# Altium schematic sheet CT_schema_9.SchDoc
size 147 x 119 mm
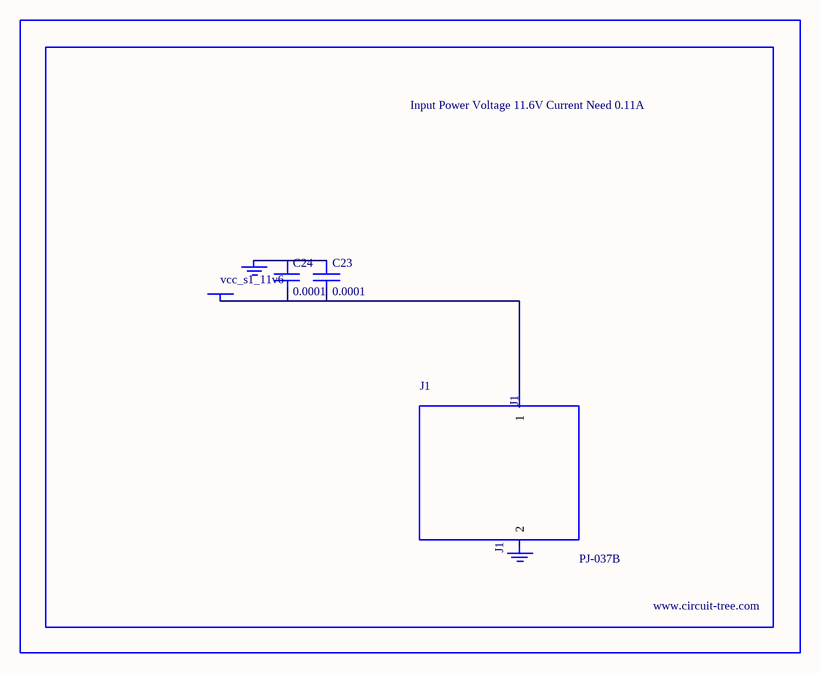
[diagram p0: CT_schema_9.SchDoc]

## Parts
BORDER8  (no value)
C23  0.0001  [EXV-9H]
C24  0.0001  [EXV-9H]
GND_INSTANCE_8_0  (no value)
GND_INSTANCE_8_1  (no value)
J1  PJ-037B  [PJ-037B_PACKAGE]
POWER_INSTANCE_8_0  vcc_s1_11v6

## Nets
NetC23_1: C23.1 C24.1 GND_INSTANCE_8_0.0(GND)
NetC23_2: C23.2 C24.2 J1.1 POWER_INSTANCE_8_0.0(PWR)

Not connected (* = marked no-connect by the designer): GND_INSTANCE_8_1 0(GND); J1 2

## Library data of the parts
BORDER8 = BORDER_PAGE8
C23 C24 = EDK107M035A9HAA
GND_INSTANCE_8_0 GND_INSTANCE_8_1 = GND
POWER_INSTANCE_8_0 = PWR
